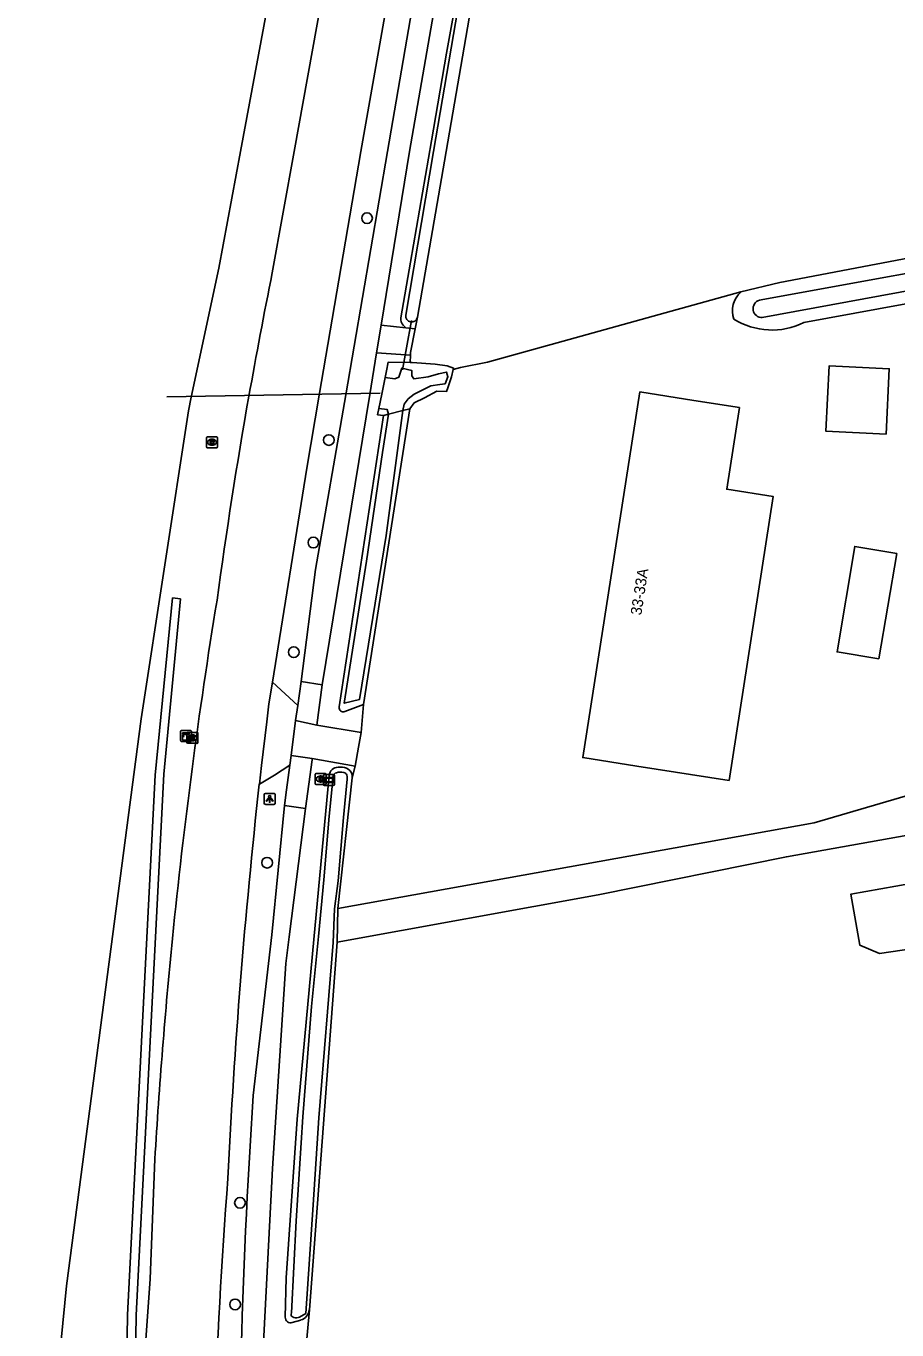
# Model space of a CAD drawing. Extents: x 162515 to 163909, y 388494 to 389773.
# Drawn here: x 162531.9 to 162611.6, y 389142.1 to 389261.5 of the extents above; entities that cross this region are included whole.
import ezdxf

# ---------------------------------------------------------------- set-up
doc = ezdxf.new("R2010")
doc.units = 0
for name, color, linetype in [('IMGEO_Boom', 7, 'Continuous'), ('IMGEO_Brandkraan', 7, 'Continuous'), ('IMGEO_Duiker', 7, 'Continuous'), ('IMGEO_Erf', 7, 'Continuous'), ('IMGEO_Fietspad_gesloten', 7, 'Continuous'), ('IMGEO_Fietspad_open', 7, 'Continuous'), ('IMGEO_Grasland_agrarisch', 7, 'Continuous'), ('IMGEO_Groenvoorziening', 7, 'Continuous'), ('IMGEO_Haag', 7, 'Continuous'), ('IMGEO_Hek', 7, 'Continuous'), ('IMGEO_Kast', 7, 'Continuous'), ('IMGEO_Lichtpunt', 7, 'Continuous'), ('IMGEO_Loofbos', 7, 'Continuous'), ('IMGEO_Oever', 7, 'Continuous'), ('IMGEO_Pand', 7, 'Continuous'), ('IMGEO_Pand_nummerreeks', 7, 'Continuous'), ('IMGEO_Rijbaan_lokaal_gesloten', 7, 'Continuous'), ('IMGEO_Rijbaan_lokaal_open', 7, 'Continuous'), ('IMGEO_Rijbaan_regionaal_gesloten', 7, 'Continuous'), ('IMGEO_Rioolput', 7, 'Continuous'), ('IMGEO_Verklikker', 7, 'Continuous'), ('IMGEO_Voetpad_open', 7, 'Continuous'), ('IMGEO_Waterloop', 7, 'Continuous')]:
    doc.layers.add(name, color=color, linetype=linetype)

msp = doc.modelspace()

# ---------------------------------------------------------------- linework, layer by layer
at = {"layer": 'IMGEO_Boom'}
for centre in [(162563.1, 389243.89), (162559.6, 389223.58), (162558.19, 389214.2), (162556.39, 389204.17), (162553.95, 389184.9), (162551.47, 389153.78), (162551.02, 389144.48)]:
    msp.add_circle(centre, 0.489, dxfattribs=at)
at = {"layer": 'IMGEO_Brandkraan'}
for p, q in [((162558.36, 389192.14), (162558.36, 389192.99)), ((162558.43, 389193.06), (162559.29, 389193.06)), ((162559.29, 389192.06), (162558.43, 389192.06)), ((162558.85, 389192.84), (162558.87, 389192.84)), ((162558.87, 389192.28), (162558.85, 389192.28)), ((162559.36, 389192.99), (162559.36, 389192.14))]:
    msp.add_line(p, q, dxfattribs=at)
for points in [[(162558.36, 389192.14), (162558.36, 389192.99)], [(162558.43, 389193.06), (162559.29, 389193.06)], [(162559.29, 389192.06), (162558.43, 389192.06)], [(162558.71, 389192.76), (162558.71, 389192.36), (162558.92, 389192.36)], [(162558.94, 389192.76), (162558.71, 389192.76)], [(162558.89, 389192.68), (162558.83, 389192.68), (162558.83, 389192.6)], [(162558.83, 389192.6), (162558.89, 389192.6)], [(162558.9, 389192.53), (162558.83, 389192.53), (162558.83, 389192.45)], [(162558.83, 389192.45), (162558.9, 389192.45)], [(162559.36, 389192.99), (162559.36, 389192.14)]]:
    msp.add_lwpolyline(points, dxfattribs=at)
for centre, radius, start, end in [((162558.44, 389192.99), 0.0765, 91.552, 178.448), ((162558.44, 389192.99), 0.0765, 91.552, 178.448), ((162558.44, 389192.14), 0.0765, 181.552, 268.448), ((162558.44, 389192.14), 0.0765, 181.552, 268.448), ((162558.89, 389192.64), 0.0379, 267.8285, 90.9355), ((162558.9, 389192.49), 0.0404, 269.8759, 90.5077), ((162558.93, 389192.61), 0.251, 268.6676, 293.5347), ((162558.94, 389192.62), 0.145, 59.4692, 91.5367), ((162558.97, 389192.66), 0.0922, 285.5137, 58.1501), ((162558.97, 389192.47), 0.105, 301.3115, 78.989), ((162559.28, 389192.99), 0.0765, 1.552, 88.448), ((162559.28, 389192.99), 0.0765, 1.552, 88.448), ((162559.28, 389192.14), 0.0765, 271.552, 358.448), ((162559.28, 389192.14), 0.0765, 271.552, 358.448)]:
    msp.add_arc(centre, radius, start, end, dxfattribs=at)
for centre, major_axis, ratio, start_param, end_param in [((162558.85, 389192.56), (-0.387, 0.002), 0.722429, 4.712389, 7.853982), ((162558.87, 389192.56), (-0.39, 0.002), 0.717154, 1.570796, 4.712389)]:
    msp.add_ellipse(centre, major_axis=major_axis, ratio=ratio, start_param=start_param, end_param=end_param, dxfattribs=at)
at = {"layer": 'IMGEO_Duiker'}
for points in [[(162567.18, 389234.53), (162566.7, 389232.03), (162566.36, 389230.01)], [(162544.78, 389227.55), (162564.31, 389227.86)]]:
    msp.add_lwpolyline(points, dxfattribs=at)
at = {"layer": 'IMGEO_Erf'}
for points in [[(162603.09, 389234.33), (162619.27, 389237.29), (162659.89, 389244.91), (162683.32, 389250), (162697.36, 389252.94), (162712.68, 389256.54)], [(162567.01, 389226.45), (162567.42, 389226.98), (162568.35, 389227.45), (162569.48, 389228.04), (162570.37, 389228.01), (162570.5, 389228.37), (162570.83, 389229.37), (162571, 389230.04)], [(162567.01, 389226.45), (162562.78, 389199.39)], [(162561.74, 389192.66), (162560.44, 389180.72)]]:
    msp.add_lwpolyline(points, dxfattribs=at)
for centre, radius, start, end in [((162598.84, 389235.4), 2.29, 131.1963, 198.9033), ((162600.18, 389240.25), 6.6, 237.9423, 296.2073)]:
    msp.add_arc(centre, radius, start, end, dxfattribs=at)
at = {"layer": 'IMGEO_Fietspad_gesloten'}
for points in [[(162590.51, 389382), (162587.31, 389370.06), (162582.8, 389349.85), (162573.64, 389300.34), (162564.98, 389250), (162561.15, 389227.73), (162558.39, 389211.74), (162557.06, 389201.5)], [(162564.38, 389234.08), (162566.99, 389250), (162579.65, 389322.8), (162581.07, 389329.83)], [(162558.98, 389201.18), (162563.35, 389227.76), (162563.97, 389231.55)], [(162557.06, 389201.5), (162558.98, 389201.18)]]:
    msp.add_lwpolyline(points, dxfattribs=at)
at = {"layer": 'IMGEO_Fietspad_open'}
for points in [[(162556.75, 389199.28), (162557.06, 389201.5)], [(162558.98, 389201.18), (162558.5, 389197.48)]]:
    msp.add_lwpolyline(points, dxfattribs=at)
at = {"layer": 'IMGEO_Grasland_agrarisch'}
for points in [[(162693.72, 389197.47), (162611.51, 389182.75), (162607.38, 389182.01), (162608.21, 389177.36), (162610.01, 389176.59), (162626.45, 389179), (162636.05, 389150.69)], [(162557.82, 389143.98), (162560.36, 389177.64)], [(162557.26, 389137.71), (162557.82, 389143.98)]]:
    msp.add_lwpolyline(points, dxfattribs=at)
at = {"layer": 'IMGEO_Groenvoorziening'}
for points in [[(162566.2, 389234.76), (162567.09, 389239.85), (162569.01, 389250.96), (162570.37, 389258.98), (162572.21, 389269.08), (162574.13, 389279.62), (162574.58, 389282.09)], [(162566.66, 389233.85), (162566.42, 389234.09)], [(162567.06, 389230.69), (162565.04, 389230.72), (162564.87, 389229.9), (162564.75, 389229.29)], [(162560.54, 389199.16), (162564.61, 389225.82)], [(162564.19, 389226.47), (162564.07, 389225.9), (162564.61, 389225.82)], [(162562.78, 389199.39), (162561.06, 389198.73)], [(162562.78, 389199.39), (162562.56, 389196.81)], [(162560.86, 389193.64), (162560.46, 389193.64)], [(162562, 389193.73), (162561.74, 389192.66)], [(162559.64, 389192.9), (162558.24, 389177.88), (162556.7, 389161.42), (162555.71, 389146.9), (162555.61, 389143.31)], [(162556.26, 389142.82), (162557.05, 389143.05)]]:
    msp.add_lwpolyline(points, dxfattribs=at)
for centre, radius, start, end in [((162566.98, 389234.64), 0.792, 171.2834, 224.9271), ((162560.93, 389199.1), 0.391, 171.4733, 289.5275), ((162560.45, 389192.82), 0.821, 89.7852, 174.8108), ((162560.86, 389192.75), 0.89, 353.7394, 89.8941), ((162556.12, 389143.3), 0.504, 178.4771, 286.5742), ((162556.74, 389144.09), 1.08, 286.6011, 354.0435)]:
    msp.add_arc(centre, radius, start, end, dxfattribs=at)
at = {"layer": 'IMGEO_Haag'}
msp.add_lwpolyline([(162546.02, 389209.04), (162545.3, 389209.14), (162543.7, 389192.92), (162541.17, 389143.52), (162540.73, 389115.61), (162540.92, 389107.45), (162541.71, 389107.47), (162541.53, 389115.62), (162541.96, 389143.49), (162544.5, 389193), (162546.02, 389209.04)], dxfattribs=at)
at = {"layer": 'IMGEO_Hek'}
for points in [[(162693.72, 389197.47), (162611.51, 389182.75)], [(162611.51, 389182.75), (162607.38, 389182.01), (162608.21, 389177.36), (162610.01, 389176.59), (162626.45, 389179), (162636.05, 389150.69)]]:
    msp.add_lwpolyline(points, dxfattribs=at)
at = {"layer": 'IMGEO_Kast'}
for p, q in [((162546.03, 389196.08), (162546.03, 389196.92)), ((162546.03, 389196.92), (162546.03, 389196.08)), ((162546.1, 389197), (162546.94, 389197)), ((162546.94, 389197), (162546.1, 389197)), ((162547.03, 389196.93), (162547.03, 389196.09)), ((162547.03, 389196.09), (162547.03, 389196.93)), ((162546.95, 389196), (162546.11, 389196)), ((162546.11, 389196), (162546.95, 389196))]:
    msp.add_line(p, q, dxfattribs=at)
for points in [[(162546.22, 389196.79), (162546.82, 389196.79), (162546.82, 389196.71), (162546.22, 389196.71), (162546.22, 389196.79)], [(162546.22, 389196.62), (162546.82, 389196.62), (162546.82, 389196.13), (162546.22, 389196.13), (162546.22, 389196.62)]]:
    msp.add_lwpolyline(points, dxfattribs=at)
msp.add_circle((162546.31, 389196.47), 0.0377, dxfattribs=at)
for centre, start, end in [((162546.11, 389196.92), 92.4484, 184.2845), ((162546.11, 389196.92), 92.4484, 184.2845), ((162546.95, 389196.92), 2.4484, 94.2845), ((162546.95, 389196.92), 2.4484, 94.2845), ((162546.11, 389196.08), 182.4484, 274.2845), ((162546.11, 389196.08), 182.4484, 274.2845), ((162546.95, 389196.08), 272.4484, 4.2845), ((162546.95, 389196.08), 272.4484, 4.2845)]:
    msp.add_arc(centre, 0.0779, start, end, dxfattribs=at)
at = {"layer": 'IMGEO_Lichtpunt'}
for p, q in [((162553.69, 389191.14), (162553.69, 389190.34)), ((162553.69, 389191.14), (162553.69, 389190.34)), ((162554.59, 389191.24), (162553.79, 389191.24)), ((162554.59, 389191.24), (162553.79, 389191.24)), ((162554.69, 389190.34), (162554.69, 389191.14)), ((162554.69, 389190.34), (162554.69, 389191.14)), ((162553.79, 389190.24), (162554.59, 389190.24)), ((162553.79, 389190.24), (162554.59, 389190.24))]:
    msp.add_line(p, q, dxfattribs=at)
for points in [[(162554.07, 389190.81), (162554.1, 389190.78), (162553.92, 389190.52), (162553.88, 389190.55), (162554.07, 389190.81)], [(162554.28, 389190.78), (162554.32, 389190.81), (162554.5, 389190.54), (162554.46, 389190.52), (162554.28, 389190.78)], [(162554.17, 389190.76), (162554.21, 389190.76), (162554.21, 389190.44), (162554.17, 389190.44), (162554.17, 389190.76)]]:
    msp.add_lwpolyline(points, dxfattribs=at)
msp.add_circle((162554.19, 389190.94), 0.0994, dxfattribs=at)
for centre, start, end in [((162553.79, 389191.14), 90, 180), ((162553.79, 389191.14), 90, 180), ((162554.59, 389191.14), 0, 90), ((162554.59, 389191.14), 0, 90), ((162553.79, 389190.34), 180, 270), ((162553.79, 389190.34), 180, 270), ((162554.59, 389190.34), 270, 0), ((162554.59, 389190.34), 270, 360)]:
    msp.add_arc(centre, 0.0946, start, end, dxfattribs=at)
at = {"layer": 'IMGEO_Loofbos'}
for points in [[(162715.83, 389259.29), (162712.71, 389259.85), (162696.58, 389256.19), (162662.62, 389249.73), (162600.88, 389237.99), (162597.33, 389237.13)], [(162597.33, 389237.13), (162574.12, 389230.7), (162571.65, 389230.21), (162571, 389230.04)], [(162567.51, 389233.77), (162567.72, 389234.82)], [(162567.08, 389231.35), (162567.06, 389230.69)], [(162571, 389230.04), (162571.03, 389230.16), (162570.43, 389230.36), (162569.34, 389230.52), (162567.23, 389230.69), (162567.06, 389230.69)]]:
    msp.add_lwpolyline(points, dxfattribs=at)
at = {"layer": 'IMGEO_Oever'}
for points in [[(162564.61, 389225.82), (162565.08, 389225.94)], [(162566.37, 389226.28), (162567.01, 389226.45)]]:
    msp.add_lwpolyline(points, dxfattribs=at)
at = {"layer": 'IMGEO_Pand'}
for points in [[(162610.62, 389224.12), (162605.11, 389224.39), (162605.4, 389230.37), (162610.91, 389230.1), (162610.62, 389224.12)], [(162597.19, 389226.56), (162596.03, 389219.08), (162600.29, 389218.41), (162596.24, 389192.43), (162587.8, 389193.75), (162582.85, 389194.52), (162588.08, 389227.98), (162593.02, 389227.21), (162597.19, 389226.56)], [(162609.97, 389203.55), (162606.13, 389204.19), (162607.75, 389213.84), (162611.59, 389213.19), (162609.97, 389203.55)]]:
    msp.add_lwpolyline(points, dxfattribs=at)
at = {"layer": 'IMGEO_Rijbaan_lokaal_gesloten'}
for points in [[(162573.38, 389345.61), (162570.09, 389328.35), (162564.73, 389295.97), (162556.42, 389250), (162554.42, 389238.88)], [(162554.44, 389201.41), (162557.59, 389221.01), (162558.73, 389227.69), (162562.53, 389250), (162578.29, 389339.21)], [(162553.24, 389192.1), (162553.43, 389193.8), (162553.92, 389197.79), (162554.12, 389199.43), (162554.44, 389201.41)], [(162543.68, 389157.76), (162543.23, 389146.81), (162542.46, 389135.69), (162542.25, 389126.25), (162542.25, 389126.2), (162542.61, 389104.53)]]:
    msp.add_lwpolyline(points, dxfattribs=at)
for centre, radius, start, end in [((163015.64, 389145.77), 470.52, 168.5864, 169.9863), ((163016.87, 389145.52), 471.78, 169.9816, 172.2776), ((163041.94, 389128.23), 499.14, 170.6973, 174.2808), ((163134.34, 389127.62), 584.67, 173.66778, 177.21606), ((163042.46, 389128.17), 499.66, 174.2801, 176.6052), ((163178.79, 389108.91), 630.19, 175.71308, 179.85085)]:
    msp.add_arc(centre, radius, start, end, dxfattribs=at)
at = {"layer": 'IMGEO_Rijbaan_lokaal_open'}
for points in [[(162563.97, 389231.55), (162564.38, 389234.08)], [(162564.38, 389234.08), (162566.66, 389233.85)], [(162566.66, 389233.85), (162567.51, 389233.77)], [(162567.51, 389233.77), (162567.08, 389231.58), (162567.08, 389231.35)], [(162567.08, 389231.35), (162563.97, 389231.55)], [(162556.75, 389199.28), (162554.44, 389201.41)], [(162556.55, 389197.92), (162556.75, 389199.28)], [(162556.15, 389194.72), (162556.55, 389197.92)], [(162558.5, 389197.48), (162556.55, 389197.92)], [(162562.56, 389196.81), (162558.5, 389197.48)], [(162562, 389193.73), (162562.32, 389195.49), (162562.56, 389196.81)], [(162556.15, 389194.72), (162556.03, 389193.82)], [(162558.09, 389194.43), (162556.15, 389194.72)], [(162558.09, 389194.43), (162562, 389193.73)], [(162556.03, 389193.82), (162554.63, 389192.92), (162553.24, 389192.1)]]:
    msp.add_lwpolyline(points, dxfattribs=at)
at = {"layer": 'IMGEO_Rijbaan_regionaal_gesloten'}
msp.add_lwpolyline([(162531.88, 389104.73), (162531.95, 389105.58), (162532.37, 389111.58), (162532.77, 389117.59), (162535.59, 389146.19), (162542.42, 389198.07), (162546.74, 389226.24), (162547.01, 389227.51), (162549.52, 389239.31), (162551.51, 389250), (162555.54, 389271.65), (162566.49, 389328.54), (162573.3, 389367.99)], dxfattribs=at)
at = {"layer": 'IMGEO_Rioolput'}
for p, q in [((162548.41, 389222.95), (162548.41, 389223.8)), ((162548.49, 389223.88), (162549.34, 389223.88)), ((162548.9, 389223.66), (162548.92, 389223.66)), ((162548.92, 389223.1), (162548.9, 389223.1)), ((162549.41, 389223.8), (162549.41, 389222.95)), ((162549.34, 389222.88), (162548.49, 389222.88)), ((162546.61, 389195.9), (162546.61, 389196.75)), ((162546.68, 389196.83), (162547.53, 389196.83)), ((162547.61, 389196.75), (162547.61, 389195.9)), ((162547.53, 389195.83), (162546.68, 389195.83)), ((162547.09, 389196.61), (162547.12, 389196.61)), ((162547.12, 389196.05), (162547.09, 389196.05))]:
    msp.add_line(p, q, dxfattribs=at)
for points in [[(162548.41, 389222.95), (162548.41, 389223.8)], [(162548.49, 389223.88), (162549.34, 389223.88)], [(162549, 389223.58), (162548.75, 389223.58), (162548.75, 389223.18)], [(162548.75, 389223.18), (162548.87, 389223.18), (162548.87, 389223.34), (162548.88, 389223.34)], [(162548.93, 389223.5), (162548.87, 389223.5), (162548.87, 389223.42)], [(162548.87, 389223.42), (162548.92, 389223.42)], [(162548.93, 389223.31), (162549, 389223.18), (162549.14, 389223.18), (162549.08, 389223.3)], [(162549.41, 389223.8), (162549.41, 389222.95)], [(162549.34, 389222.88), (162548.49, 389222.88)], [(162546.61, 389195.9), (162546.61, 389196.75)], [(162546.68, 389196.83), (162547.53, 389196.83)], [(162547.61, 389196.75), (162547.61, 389195.9)], [(162547.53, 389195.83), (162546.68, 389195.83)], [(162547.2, 389196.52), (162546.94, 389196.53), (162546.94, 389196.13)], [(162546.94, 389196.13), (162547.07, 389196.13), (162547.07, 389196.29), (162547.08, 389196.29)], [(162547.12, 389196.45), (162547.07, 389196.45), (162547.07, 389196.36)], [(162547.07, 389196.36), (162547.12, 389196.36)], [(162547.12, 389196.26), (162547.2, 389196.13), (162547.34, 389196.13), (162547.27, 389196.25)]]:
    msp.add_lwpolyline(points, dxfattribs=at)
for centre, radius, start, end in [((162548.49, 389223.8), 0.0765, 91.552, 178.448), ((162548.49, 389223.8), 0.0765, 91.552, 178.448), ((162548.88, 389223.29), 0.0533, 26.0293, 88.6989), ((162548.91, 389223.61), 0.19, 274.7715, 282.9687), ((162548.93, 389223.4), 0.0964, 77.0061, 93.1865), ((162548.95, 389223.46), 0.0378, 276.6634, 79.6772), ((162549, 389223.47), 0.109, 350.3612, 89.416), ((162549, 389223.47), 0.112, 277.5842, 350.9817), ((162548.98, 389223.25), 0.108, 29.5134, 73.7905), ((162549.34, 389223.8), 0.0765, 1.552, 88.448), ((162549.34, 389223.8), 0.0765, 1.552, 88.448), ((162548.49, 389222.95), 0.0765, 181.552, 268.448), ((162548.49, 389222.95), 0.0765, 181.552, 268.448), ((162549.34, 389222.95), 0.0765, 271.552, 358.448), ((162549.34, 389222.95), 0.0765, 271.552, 358.448), ((162546.68, 389196.75), 0.0765, 91.552, 178.448), ((162546.68, 389196.75), 0.0765, 91.552, 178.448), ((162547.53, 389196.75), 0.0765, 1.552, 88.448), ((162547.53, 389196.75), 0.0765, 1.552, 88.448), ((162546.68, 389195.9), 0.0765, 181.552, 268.448), ((162546.68, 389195.9), 0.0765, 181.552, 268.448), ((162547.08, 389196.24), 0.0533, 26.0293, 88.6989), ((162547.13, 389196.35), 0.0964, 77.0061, 93.1865), ((162547.1, 389196.55), 0.19, 274.7715, 282.9687), ((162547.14, 389196.41), 0.0378, 276.6634, 79.6772), ((162547.19, 389196.41), 0.109, 350.3612, 89.416), ((162547.19, 389196.41), 0.112, 277.5842, 350.9817), ((162547.18, 389196.2), 0.108, 29.5134, 73.7905), ((162547.53, 389195.9), 0.0765, 271.552, 358.448), ((162547.53, 389195.9), 0.0765, 271.552, 358.448)]:
    msp.add_arc(centre, radius, start, end, dxfattribs=at)
for centre, major_axis, ratio, start_param, end_param in [((162548.9, 389223.38), (-0.387, 0.002), 0.722429, 4.712389, 7.853982), ((162548.92, 389223.38), (-0.39, 0.002), 0.717154, 1.570796, 4.712389), ((162547.09, 389196.33), (-0.387, 0.002), 0.722429, 4.712389, 7.853982), ((162547.12, 389196.33), (-0.39, 0.002), 0.717154, 1.570796, 4.712389)]:
    msp.add_ellipse(centre, major_axis=major_axis, ratio=ratio, start_param=start_param, end_param=end_param, dxfattribs=at)
at = {"layer": 'IMGEO_Verklikker'}
for p, q in [((162559.12, 389192.06), (162559.12, 389192.86)), ((162559.12, 389192.86), (162559.12, 389192.06)), ((162559.22, 389192.96), (162560.01, 389192.96)), ((162560.01, 389192.96), (162559.22, 389192.96)), ((162560.11, 389192.86), (162560.11, 389192.06)), ((162560.11, 389192.06), (162560.11, 389192.86)), ((162560.01, 389191.96), (162559.22, 389191.96)), ((162559.22, 389191.96), (162560.01, 389191.96))]:
    msp.add_line(p, q, dxfattribs=at)
for points in [[(162559.22, 389192.69), (162560, 389192.69), (162560, 389192.23), (162559.22, 389192.23), (162559.22, 389192.69)], [(162559.28, 389192.63), (162559.28, 389192.29), (162559.94, 389192.29), (162559.94, 389192.63), (162559.28, 389192.63)]]:
    msp.add_lwpolyline(points, dxfattribs=at)
for centre, start, end in [((162559.22, 389192.86), 90, 180), ((162559.22, 389192.86), 90, 180), ((162559.22, 389192.06), 180, 270), ((162559.22, 389192.06), 180, 270), ((162560.01, 389192.86), 0, 90), ((162560.01, 389192.86), 360, 90), ((162560.01, 389192.06), 270, 0), ((162560.01, 389192.06), 270, 0)]:
    msp.add_arc(centre, 0.1, start, end, dxfattribs=at)
at = {"layer": 'IMGEO_Voetpad_open'}
for points in [[(162557.46, 389189.87), (162558.08, 389194.33), (162558.09, 389194.43)], [(162555.54, 389190.15), (162555.73, 389191.57), (162556.03, 389193.82)], [(162552.68, 389163.6), (162554.37, 389178.31), (162555.54, 389190.15)], [(162553.49, 389105.71), (162553.3, 389118.24), (162553.42, 389136.84), (162554.46, 389156.91), (162555.68, 389175.67), (162555.98, 389178.13), (162557.46, 389189.87)], [(162557.46, 389189.87), (162555.54, 389190.15)]]:
    msp.add_lwpolyline(points, dxfattribs=at)
msp.add_arc((163131.14, 389124.82), 579.76, 176.16485, 181.06575, dxfattribs=at)
at = {"layer": 'IMGEO_Waterloop'}
for points in [[(162575.31, 389281.97), (162575.06, 389282), (162574.91, 389281.81), (162571.41, 389263.02), (162569.2, 389250), (162566.65, 389235.02)], [(162567.72, 389234.82), (162570.33, 389250), (162572.59, 389263.07)], [(162734.87, 389167.59), (162725.95, 389217.7), (162719.74, 389253.53), (162718.98, 389255.27), (162717.97, 389256.44), (162716.79, 389257.33), (162715.19, 389258.15), (162713.92, 389258.4), (162712.52, 389258.4), (162664.64, 389248.62), (162623.86, 389240.9), (162599.01, 389236.39)], [(162599.29, 389234.79), (162622.7, 389239.1), (162676.17, 389249.41), (162712.47, 389257.25)], [(162566.37, 389226.28), (162566.5, 389226.85), (162566.86, 389227.35), (162567.42, 389227.78), (162568.15, 389228.14), (162568.95, 389228.54), (162569.77, 389228.67), (162570.24, 389228.74), (162570.5, 389229.37), (162570.37, 389229.8), (162569.64, 389229.63), (162568.71, 389229.37), (162567.39, 389229.17), (162567.19, 389229.47), (162567.19, 389229.96), (162566.3, 389230.16), (162566, 389229.33), (162565.64, 389229.17), (162564.75, 389229.29)], [(162564.75, 389229.29), (162564.45, 389227.78), (162564.19, 389226.47)], [(162565.08, 389225.94), (162564.52, 389222.44), (162563.05, 389212.5), (162561.02, 389199.5), (162562.4, 389199.83), (162564.84, 389214.85), (162566.37, 389226.28)], [(162564.19, 389226.47), (162564.94, 389226.39), (162565.08, 389225.94)], [(162565.08, 389225.94), (162566.37, 389226.28)], [(162722.25, 389210.61), (162680.29, 389202.53), (162635.91, 389194.27), (162613.11, 389191.22), (162604.05, 389188.55), (162560.44, 389180.72)], [(162560.36, 389177.64), (162584.26, 389181.97), (162601.5, 389185.45), (162631.76, 389190.83), (162646.02, 389193.65), (162681.16, 389201.06)], [(162556.39, 389143.28), (162556.18, 389143.42), (162556.16, 389143.48), (162556.16, 389143.6), (162556.18, 389143.72), (162556.6, 389152.14), (162557.21, 389161.64), (162558.02, 389171.74), (162558.67, 389178.16), (162559.13, 389183.35), (162559.64, 389189.16), (162559.99, 389192.8)], [(162561.26, 389192.91), (162561.28, 389192.78), (162561.29, 389192.56), (162560.96, 389189.04), (162560.45, 389183.23), (162560.13, 389180.68), (162559.99, 389177.6), (162558.7, 389161.55), (162558.17, 389153.6), (162557.5, 389143.65)], [(162560.44, 389180.72), (162560.36, 389177.64)], [(162557.5, 389143.65), (162556.93, 389143.32)]]:
    msp.add_lwpolyline(points, dxfattribs=at)
for centre, radius, start, end in [((162599.26, 389235.61), 0.817, 107.3408, 271.9908), ((162567.19, 389234.93), 0.545, 170.3959, 347.8092), ((162560.69, 389191.7), 1.49, 79.0154, 104.9344), ((162560.46, 389192.66), 0.5, 108.6234, 163.6576), ((162560.94, 389192.83), 0.328, 14.1619, 84.4379), ((162556.62, 389143.87), 0.626, 248.3052, 300.0901)]:
    msp.add_arc(centre, radius, start, end, dxfattribs=at)

# ---------------------------------------------------------------- texts
at = {"layer": 'IMGEO_Pand_nummerreeks'}
msp.add_text('33-33A', height=1, rotation=81.1287, dxfattribs=at).set_placement((162588.2, 389207.5))

doc.saveas('drawing.dxf')
